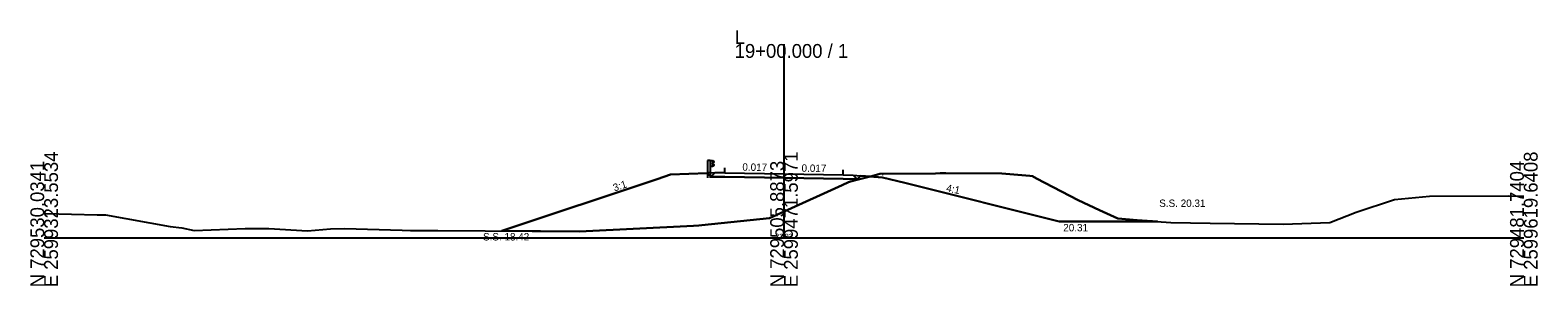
# Model space of a CAD drawing. Extents: x -26 to 3303, y -10 to 9555.
# Drawn here: x 997.2 to 1302.8, y 7990.3 to 8042 of the extents above; entities that cross this region are included whole.
import ezdxf

# ---------------------------------------------------------------- set-up
doc = ezdxf.new("R2010")
doc.units = 0
for name, color, linetype in [('Exist Cross Section Cell', 7, 'Continuous'), ('Exist XS Center Line Elevation Label', 7, 'Continuous'), ('Exist XS Ground Line', 7, 'Continuous'), ('Prop XS Ditch Slope Text', 7, 'Continuous'), ('Prop XS Ditch Standard Text', 7, 'Continuous'), ('Prop XS Dump Level', 7, 'Continuous'), ('Prop XS Earthwork Shape', 7, 'Continuous'), ('Prop XS EOT Tick Mark', 7, 'Continuous'), ('Prop XS Finish Grade', 7, 'Continuous'), ('Prop XS Finish Grade Earthwork', 7, 'Continuous'), ('Prop XS Finish Grade Paved Shoulder', 7, 'Continuous'), ('Prop XS Finish Grade Pavement', 7, 'Continuous'), ('Prop XS Pvmt Edge Slope', 7, 'Continuous'), ('Prop XS SE Text', 7, 'Continuous'), ('Prop XS Side Slope Text', 7, 'Continuous'), ('Prop XS SS Elevation Text', 7, 'Continuous'), ('Prop XS Subgrade Earthwork', 7, 'Continuous'), ('Typical Guardrail CELL', 7, 'Continuous')]:
    doc.layers.add(name, color=color, linetype=linetype)

msp = doc.modelspace()

# ---------------------------------------------------------------- linework, layer by layer
at = {"layer": 'Exist Cross Section Cell'}
for p, q in [((1150, 8000), (1150, 8039.25)), ((1000, 8000), (1150, 8000)), ((1150, 8000), (1300, 8000))]:
    msp.add_line(p, q, dxfattribs=at)
at = {"layer": 'Exist XS Ground Line'}
msp.add_lwpolyline([(1000, 8004.95), (1000.35, 8004.97), (1010.72, 8004.68), (1012.42, 8004.7), (1025.53, 8002.32), (1027.91, 8002.03), (1030.4, 8001.51), (1040.75, 8001.92), (1045.57, 8001.88), (1053.37, 8001.45), (1058.03, 8001.82), (1060.9, 8001.88), (1072.56, 8001.54), (1074.28, 8001.53), (1079.8, 8001.49), (1108.55, 8001.33), (1131.63, 8002.44), (1132.73, 8002.49), (1133.33, 8002.58), (1147.05, 8003.98), (1150, 8005.33), (1161.8, 8010.71), (1163.07, 8011.31), (1163.47, 8011.4), (1169.42, 8012.94), (1180.72, 8013.06), (1181.69, 8013.08), (1182.8, 8013.08), (1194.15, 8013.06), (1199.82, 8012.54), (1200.38, 8012.49), (1201.22, 8012.05), (1209.62, 8007.64), (1213.94, 8005.62), (1217.68, 8003.91), (1221.62, 8003.61), (1228.46, 8003.11), (1236.38, 8002.98), (1251.21, 8002.77), (1260.65, 8003.09), (1265.98, 8005.23), (1273.75, 8007.79), (1280.86, 8008.44), (1296.86, 8008.53), (1300, 8008.42)], dxfattribs=at)
at = {"layer": 'Prop XS Dump Level'}
for p, q in [((1138, 8013.17), (1150, 8012.96)), ((1150, 8012.96), (1162, 8012.76))]:
    msp.add_line(p, q, dxfattribs=at)
at = {"layer": 'Prop XS Earthwork Shape'}
for points in [[(1134.43, 8013.13), (1127, 8012.82), (1124.3, 8011.92), (1092.81, 8001.42), (1108.55, 8001.33), (1131.63, 8002.44), (1132.73, 8002.49), (1133.33, 8002.58), (1147.05, 8003.98), (1150, 8005.33), (1161.8, 8010.71), (1163.07, 8011.31), (1163.47, 8011.4), (1167.54, 8012.45), (1165.57, 8012.6), (1164.85, 8011.88), (1164, 8011.89), (1162, 8011.93), (1150, 8012.13), (1138, 8012.34), (1136, 8012.37), (1135.18, 8012.38)], [(1164, 8011.89), (1164.85, 8011.88), (1165.57, 8012.6), (1167.54, 8012.45), (1163.47, 8011.4), (1163.07, 8011.31), (1161.8, 8010.71), (1150, 8005.33), (1147.05, 8003.98), (1133.33, 8002.58), (1132.73, 8002.49), (1131.63, 8002.44), (1108.55, 8001.33), (1092.81, 8001.42), (1124.3, 8011.92), (1127, 8012.82), (1134.43, 8013.13), (1135.18, 8012.38), (1136, 8012.37), (1138, 8012.34), (1150, 8012.13), (1162, 8011.93)], [(1201.22, 8012.05), (1209.62, 8007.64), (1213.94, 8005.62), (1217.68, 8003.91), (1221.62, 8003.61), (1225.71, 8003.31), (1205.81, 8003.31), (1174.52, 8011.13), (1170, 8012.26), (1167.54, 8012.45), (1169.42, 8012.94), (1180.72, 8013.06), (1181.69, 8013.08), (1182.8, 8013.08), (1194.15, 8013.06), (1199.82, 8012.54), (1200.38, 8012.49)], [(1174.52, 8011.13), (1205.81, 8003.31), (1225.71, 8003.31), (1221.62, 8003.61), (1217.68, 8003.91), (1213.94, 8005.62), (1209.62, 8007.64), (1201.22, 8012.05), (1200.38, 8012.49), (1199.82, 8012.54), (1194.15, 8013.06), (1182.8, 8013.08), (1181.69, 8013.08), (1180.72, 8013.06), (1169.42, 8012.94), (1167.54, 8012.45), (1170, 8012.26)]]:
    msp.add_lwpolyline(points, close=True, dxfattribs=at)
at = {"layer": 'Prop XS EOT Tick Mark'}
for p, q in [((1138, 8013.17), (1138, 8014.17)), ((1162, 8012.76), (1162, 8013.76))]:
    msp.add_line(p, q, dxfattribs=at)
at = {"layer": 'Prop XS Finish Grade'}
for p, q in [((1136, 8013.2), (1134.43, 8013.13)), ((1164, 8012.73), (1165.57, 8012.6))]:
    msp.add_line(p, q, dxfattribs=at)
at = {"layer": 'Prop XS Finish Grade Earthwork'}
for p, q in [((1124.3, 8011.92), (1092.81, 8001.42)), ((1127, 8012.82), (1124.3, 8011.92)), ((1134.43, 8013.13), (1127, 8012.82)), ((1165.57, 8012.6), (1170, 8012.26)), ((1170, 8012.26), (1174.52, 8011.13)), ((1174.52, 8011.13), (1205.81, 8003.31)), ((1225.71, 8003.31), (1205.81, 8003.31))]:
    msp.add_line(p, q, dxfattribs=at)
at = {"layer": 'Prop XS Finish Grade Paved Shoulder'}
for p, q in [((1138, 8013.17), (1136, 8013.2)), ((1162, 8012.76), (1164, 8012.73))]:
    msp.add_line(p, q, dxfattribs=at)
at = {"layer": 'Prop XS Finish Grade Pavement'}
for p, q in [((1138, 8013.17), (1150, 8012.96)), ((1150, 8012.96), (1162, 8012.76))]:
    msp.add_line(p, q, dxfattribs=at)
at = {"layer": 'Prop XS Pvmt Edge Slope'}
for p, q in [((1135.18, 8012.38), (1134.43, 8013.13)), ((1136, 8013.2), (1135.18, 8012.38)), ((1164, 8012.73), (1164.85, 8011.88)), ((1164.85, 8011.88), (1165.57, 8012.6))]:
    msp.add_line(p, q, dxfattribs=at)
at = {"layer": 'Prop XS Subgrade Earthwork'}
for p, q in [((1135.18, 8012.38), (1134.43, 8013.13)), ((1136, 8012.37), (1135.18, 8012.38)), ((1138, 8012.34), (1136, 8012.37)), ((1150, 8012.13), (1138, 8012.34)), ((1162, 8011.93), (1150, 8012.13)), ((1162, 8011.93), (1164, 8011.89)), ((1164.85, 8011.88), (1165.57, 8012.6)), ((1164, 8011.89), (1164.85, 8011.88))]:
    msp.add_line(p, q, dxfattribs=at)
at = {"layer": 'Typical Guardrail CELL'}
for p, q in [((1135, 8015.65), (1134.5, 8015.65)), ((1134.5, 8015.65), (1134.5, 8013.16)), ((1135, 8015.65), (1135, 8013.16)), ((1135, 8015.65), (1135.5, 8015.65)), ((1135.5, 8015.65), (1135.5, 8014.49)), ((1135.5, 8015.65), (1135.79, 8015.44)), ((1135.5, 8015.11), (1135.79, 8015.31)), ((1135.5, 8015.07), (1135.5, 8015.11)), ((1135.5, 8015.07), (1135.5, 8015.02)), ((1135.5, 8015.02), (1135.79, 8014.82)), ((1135, 8013.16), (1134.5, 8013.16)), ((1134.5, 8013.16), (1134.5, 8012.15)), ((1135, 8014.49), (1135.5, 8014.49)), ((1135, 8013.16), (1135, 8012.15)), ((1135.5, 8014.49), (1135.79, 8014.69))]:
    msp.add_line(p, q, dxfattribs=at)
for centre, start, end in [((1135.74, 8015.38), 304.9888, 54.997), ((1135.74, 8014.75), 304.9634, 54.9941)]:
    msp.add_arc(centre, 0.0776, start, end, dxfattribs=at)

# ---------------------------------------------------------------- texts
at = {"layer": 'Exist Cross Section Cell'}
for s, p in [('L', (1140, 8039.25)), ('19+00.000 / 1', (1140, 8036.45))]:
    msp.add_text(s, height=2.8, dxfattribs=at).set_placement(p)
for s, p in [('N 729530.0341', (1000, 7990)), ('E 2599323.5534', (1002.8, 7990)), ('N 729505.8873', (1150, 7990)), ('E 2599471.5971', (1152.8, 7990)), ('N 729481.7404', (1300, 7990)), ('E 2599619.6408', (1302.8, 7990))]:
    msp.add_text(s, height=2.8, rotation=90, dxfattribs=at).set_placement(p)
at = {"layer": 'Exist XS Center Line Elevation Label'}
msp.add_text('22.33', height=1, dxfattribs=at).set_placement((1148.27, 7999.83))
at = {"layer": 'Prop XS Ditch Slope Text'}
msp.add_text('4:1', height=1.5, rotation=348.3911, dxfattribs=at).set_placement((1182.79, 8009.42))
at = {"layer": 'Prop XS Ditch Standard Text'}
msp.add_text('20.31', height=1.5, dxfattribs=at).set_placement((1206.62, 8001.33))
at = {"layer": 'Prop XS Dump Level'}
for s, height, p in [('Case1', 0.04, (1130, 8012.9)), ('Eop', 0.3, (1169.42, 8012.64)), ('Eop', 0.3, (1169.42, 8012.64)), ('Case1', 0.04, (1170, 8012.22))]:
    msp.add_text(s, height=height, dxfattribs=at).set_placement(p)
at = {"layer": 'Prop XS SE Text'}
for p in [(1141.55, 8013.61), (1153.55, 8013.4)]:
    msp.add_text('0.017', height=1.5, rotation=359.0237, dxfattribs=at).set_placement(p)
at = {"layer": 'Prop XS Side Slope Text'}
msp.add_text('3:1', height=1.5, rotation=18.4349, dxfattribs=at).set_placement((1115.63, 8009.39))
at = {"layer": 'Prop XS SS Elevation Text'}
for s, p in [('S.S. 20.31', (1226.08, 8006.27)), ('S.S. 18.42', (1088.98, 7999.48))]:
    msp.add_text(s, height=1.5, dxfattribs=at).set_placement(p)

doc.saveas('drawing.dxf')
